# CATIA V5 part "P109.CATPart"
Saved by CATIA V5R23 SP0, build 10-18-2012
Part number: P109
Definition: Came Plateau
Description: Came Plateau
Bounding box of the stored display mesh (mm): x -12.5 to 12.5, y -27 to 27, z -27 to 27
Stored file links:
  C:\wamp\www\COURS\CONCEPTION GMP1\TITRE 02-SEMESTRE 2\03-TP7-PRESSE MECANIQUE\eleve\P109.CATPart
  C:\Program Files\Dassault Systemes\B19\win_b64\reffiles\standard\MetricThickPitch.txt
  C:\wamp\www\COURS\CONCEPTION GMP1\TITRE 02-SEMESTRE 2\03-TP7-PRESSE MECANIQUE\eleve\05-LICP-T02-E-S08-P107.CATPart
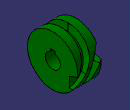
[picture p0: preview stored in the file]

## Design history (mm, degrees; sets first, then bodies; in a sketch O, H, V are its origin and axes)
Set1
  Combine1: Curve1 Sketch7, Curve2 edge [face of Pad1 | face of Pad1]
  Sketch1 on face of Groove1, origin (0, 0, 0), H (1, 0, 0), V (0, 0, 1)
    line L1 (-4, 28) -> (4, 28)
    line L2 (4, 28) -> (4, 19)
    line L3 (4, 19) -> (-4, 19)
    line L4 (-4, 19) -> (-4, 28)
    length L4 = 9
    length L1 = 8
    distance L1 H = 28
    horizontal: L1 H, L3 H
    vertical: L2 V, L4 V
    symmetry: L4 L2 V
  Line1 "Axe Z": stored without definition
  Point1: type OnCurve, Support Combine1, RefPoint {extremum Reference Combine1, Direction (0, 0, 1), Direction2 (0, 0, 1), Direction3 (0, 0, 1)}, Ratio 0.5
  Split1: ToCut Combine1, Cutting Point1
  Combine2: Curve1 Sketch6, Curve2 edge [face of Pad1 | face of Pad1]
  Split2: ToCut Combine2, Cutting Sketch6
  Sketch2 on face of Groove1, origin (0, 0, 0), H (1, 0, 0), V (0, 0, 1)
    line L1 (-4, -19) -> (4, -19)
    line L2 (4, -19) -> (4, -28)
    line L3 (4, -28) -> (-4, -28)
    line L4 (-4, -28) -> (-4, -19)
    length L1 = 8
    length L2 = 9
    distance L3 H = 28
    horizontal: L1 H, L3 H
    vertical: L2 V, L4 V
    symmetry: L2 L4 V
  Extract1: ExtractElem edge [face of Pad1 | face of Slot1]
  DatumCurve1: linked copy from another document
  Split3: ToCut DatumCurve1, Cutting Sketch7
  DatumSurface1
  Plane1 to Plane3: stored without definition
Body1 (main body)
  Sketch3 on yz-plane, origin (0, 0, 0), H (0, 1, 0), V (0, 0, 1)
    circle A1 centre (0, 0) radius 27
    radius A1 = 27
  Pad1: profile Sketch3, direction (1, 0, 0), length 12.5, mirrored extent
  Sketch4 on zx-plane, origin (0, 0, 0), H (-1, 0, 0), V (0, 0, 1)
    line L1 (-4, 27) -> (4, 27)
    line L2 (4, 27) -> (4, 19)
    line L3 (4, 19) -> (-4, 19)
    line L4 (-4, 19) -> (-4, 27)
    distance L4 L2 = 8
    length L2 = 8
    distance L1 H = 27
    horizontal: L1 H, L3 H
    vertical: L2 V, L4 V
    symmetry: L4 L2 V
  Groove1: profile Sketch4, axis axis of face of Pad1, angle 180
  Slot1: profile Sketch1, centre curve Split3
  Slot2: profile Sketch2, centre curve Split2
  Sketch5 on face of Pad1, origin (12.5, 0, 0), H (0, 1, 0), V (0, 0, 1)
    arc A1 centre (0, 0) radius 8 from (-2.5, 7.5993) to (2.5, 7.5993) ccw
    line L1 (-2.5, 10) -> (2.5, 10)
    line L2 (2.5, 10) -> (2.5, 7.5993)
    line L3 (-2.5, 7.5993) -> (-2.5, 10)
    length L1 = 5
    distance L1 H = 10
    radius A1 = 8
    horizontal: L1 H
    vertical: L2 V, L3 V
    symmetry: L2 L3 V
  Pocket1: profile Sketch5, direction (-1, 0, 0), through (limit type 6)
  Sketch6 on zx-plane, origin (0, 0, 0), H (-1, 0, 0), V (0, 0, 1)
    arc A1 centre (58, -27) radius 55 from (18.7072, 11.4848) to (3, -27) ccw
    point P3 (3, -27)
    construction line L1 (3, 11.3613) -> (3, -60.7792)
    distance P3 H = 27
    distance V P3 = 3
    distance V L1 = 3
    radius A1 = 55
    vertical: L1 V
    tangency: L1 A1
  Sketch7 on zx-plane, origin (0, 0, 0), H (-1, 0, 0), V (0, 0, 1)
    arc A1 centre (-58, 27) radius 55 from (-22.8841, -15.3306) to (-3, 27) ccw
    point P3 (-3, 27)
    construction line L1 (-3, 33.9574) -> (-3, -10.7324)
    distance P3 H = 27
    distance P3 V = 3
    distance V L1 = 3
    radius A1 = 55
    vertical: L1 V
    tangency: A1 L1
